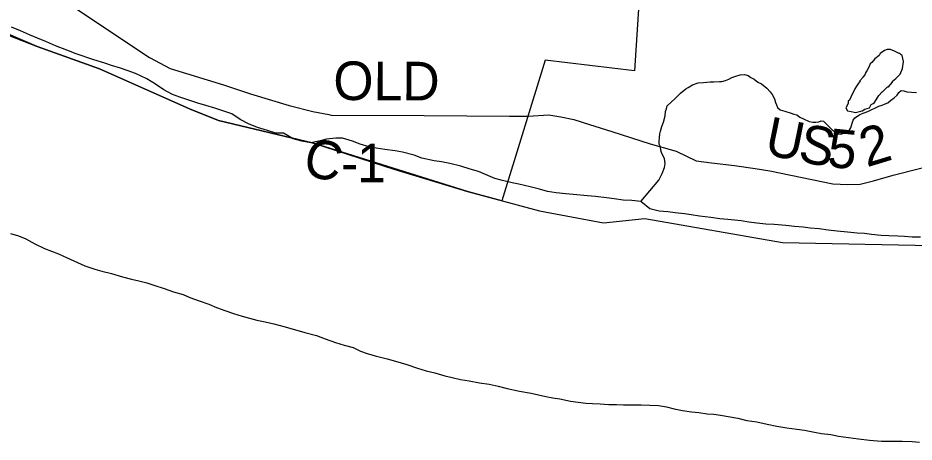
# Model space of a CAD drawing. Extents: x 1949938.81 to 1949945.61, y 152207.65 to 152214.09.
# Drawn here: x 1949941.387 to 1949942.704, y 152207.717 to 152208.341 of the extents above; entities that cross this region are included whole.
import ezdxf

# ---------------------------------------------------------------- set-up
doc = ezdxf.new("R2010")
doc.units = 0
for name, color, linetype in [('GM_X_City_Street', 7, 'Continuous'), ('GM_X_Corporation', 7, 'Continuous'), ('GM_X_County', 7, 'Continuous'), ('GM_X_County_Road', 7, 'Continuous'), ('GM_X_County_Road_Text', 7, 'Continuous'), ('GM_X_Major_River', 7, 'Continuous'), ('GM_X_Minor_Lake', 7, 'Continuous'), ('GM_X_Minor_River', 7, 'Continuous'), ('GM_X_Township', 7, 'Continuous')]:
    doc.layers.add(name, color=color, linetype=linetype)

msp = doc.modelspace()

# ---------------------------------------------------------------- linework, layer by layer
at = {"layer": 'GM_X_City_Street'}
msp.add_lwpolyline([(1949941.4607, 152208.3637), (1949941.4704, 152208.3561), (1949941.5442, 152208.3067), (1949941.5804, 152208.2827), (1949941.6108, 152208.2664), (1949941.689, 152208.2426), (1949941.7287, 152208.2292), (1949941.7858, 152208.2124), (1949941.8203, 152208.2034), (1949941.8437, 152208.1989)], dxfattribs=at)
at = {"layer": 'GM_X_Corporation'}
msp.add_lwpolyline([(1949942.1062, 152209.4059), (1949942.0896, 152209.1325), (1949942.3484, 152209.1187), (1949942.2928, 152208.2633), (1949942.1618, 152208.279), (1949942.0982, 152208.0722), (1949942.0477, 152208.0858), (1949941.8214, 152208.1567), (1949941.682, 152208.19), (1949941.6393, 152208.2075), (1949941.5072, 152208.2663), (1949941.4156, 152208.2992), (1949941.1468, 152208.4145), (1949940.9962, 152208.5094), (1949940.8932, 152208.5894), (1949940.8285, 152208.6338), (1949940.6601, 152208.7875), (1949940.5757, 152208.8589), (1949940.4882, 152208.9716), (1949940.3947, 152209.1158), (1949940.3383, 152209.2145)], dxfattribs=at)
at = {"layer": 'GM_X_County'}
msp.add_lwpolyline([(1949940.3383, 152209.2145), (1949940.3947, 152209.1158), (1949940.4882, 152208.9716), (1949940.5757, 152208.8589), (1949940.6601, 152208.7875), (1949940.8285, 152208.6338), (1949940.8932, 152208.5894), (1949940.9962, 152208.5094), (1949941.1468, 152208.4145), (1949941.2284, 152208.3724), (1949941.4156, 152208.2992), (1949941.5072, 152208.2663), (1949941.6393, 152208.2075), (1949941.682, 152208.19), (1949941.8214, 152208.1567), (1949941.9395, 152208.1188), (1949942.0477, 152208.0858), (1949942.1534, 152208.0573), (1949942.2476, 152208.0399), (1949942.3082, 152208.046), (1949942.5103, 152208.0107), (1949942.8268, 152208.0046)], dxfattribs=at)
at = {"layer": 'GM_X_County_Road'}
msp.add_lwpolyline([(1949941.8437, 152208.1989), (1949941.8476, 152208.1981), (1949941.9841, 152208.1975), (1949942.1095, 152208.1966), (1949942.1364, 152208.1966), (1949942.1671, 152208.1984), (1949942.1849, 152208.1956), (1949942.2041, 152208.1914), (1949942.227, 152208.1844), (1949942.2598, 152208.1741), (1949942.316, 152208.1558), (1949942.3541, 152208.145), (1949942.3838, 152208.131), (1949942.406, 152208.1277), (1949942.4398, 152208.124), (1949942.4703, 152208.1195), (1949942.4917, 152208.1162), (1949942.5844, 152208.0972), (1949942.6061, 152208.0962), (1949942.6245, 152208.0966), (1949942.6444, 152208.1013), (1949942.6732, 152208.1097), (1949942.7524, 152208.1298)], dxfattribs=at)
at = {"layer": 'GM_X_Major_River'}
for points in [[(1949942.0877, 152208.105), (1949942.0639, 152208.1152), (1949942.0518, 152208.1186), (1949942.0378, 152208.1232), (1949942.0215, 152208.127), (1949942.0094, 152208.1293), (1949941.9988, 152208.1308), (1949941.9807, 152208.135), (1949941.9693, 152208.1391), (1949941.9523, 152208.1437), (1949941.9413, 152208.1456), (1949941.9262, 152208.1475), (1949941.9134, 152208.1497), (1949941.9031, 152208.1516), (1949941.8899, 152208.1554), (1949941.8786, 152208.1596), (1949941.8642, 152208.1641), (1949941.8544, 152208.1641), (1949941.8407, 152208.1626), (1949941.829, 152208.1596), (1949941.8173, 152208.1573), (1949941.8044, 152208.16), (1949941.7916, 152208.1634), (1949941.7773, 152208.1716), (1949941.7659, 152208.1713), (1949941.7538, 152208.1755), (1949941.739, 152208.1797), (1949941.7258, 152208.1854), (1949941.7137, 152208.1918), (1949941.7012, 152208.1998), (1949941.688, 152208.2043), (1949941.6762, 152208.2085), (1949941.663, 152208.2123), (1949941.6517, 152208.2157), (1949941.6414, 152208.2191), (1949941.6248, 152208.2244), (1949941.6142, 152208.2282), (1949941.6017, 152208.2354), (1949941.5893, 152208.2434), (1949941.5764, 152208.2514), (1949941.5598, 152208.2593), (1949941.5477, 152208.2639), (1949941.5378, 152208.2669), (1949941.5246, 152208.2711), (1949941.5148, 152208.2745), (1949941.4989, 152208.2794), (1949941.4728, 152208.2881), (1949941.4592, 152208.2935), (1949941.4425, 152208.2999), (1949941.4293, 152208.3056), (1949941.4157, 152208.3113), (1949941.4043, 152208.3162), (1949941.3907, 152208.3219), (1949941.3779, 152208.3272)], [(1949942.7132, 152208.0188), (1949942.7011, 152208.0188), (1949942.6898, 152208.0196), (1949942.6799, 152208.02), (1949942.6667, 152208.0207), (1949942.6554, 152208.0211), (1949942.6414, 152208.0226), (1949942.6308, 152208.0238), (1949942.6202, 152208.0245), (1949942.6062, 152208.0261), (1949942.5907, 152208.0276), (1949942.5775, 152208.0291), (1949942.5646, 152208.031), (1949942.551, 152208.0321), (1949942.5408, 152208.0333), (1949942.5283, 152208.0344), (1949942.5154, 152208.0356), (1949942.498, 152208.0371), (1949942.4859, 152208.0378), (1949942.4727, 152208.0394), (1949942.461, 152208.0409), (1949942.4496, 152208.0424), (1949942.43, 152208.0447), (1949942.4186, 152208.0458), (1949942.4054, 152208.0477), (1949942.3884, 152208.0496), (1949942.3763, 152208.0515), (1949942.3664, 152208.053), (1949942.3528, 152208.0545), (1949942.3422, 152208.0557), (1949942.3294, 152208.0568), (1949942.3157, 152208.0602), (1949942.3025, 152208.0712), (1949942.2889, 152208.0727), (1949942.2764, 152208.0731), (1949942.2632, 152208.075), (1949942.2518, 152208.0765), (1949942.2356, 152208.0784), (1949942.2242, 152208.0796), (1949942.203, 152208.0815), (1949942.1921, 152208.0822), (1949942.1781, 152208.0837), (1949942.1652, 152208.086), (1949942.1535, 152208.0891), (1949942.1395, 152208.0925), (1949942.1232, 152208.0966), (1949942.1134, 152208.0985), (1949942.099, 152208.102), (1949942.0877, 152208.105)], [(1949941.3763, 152208.0238), (1949941.388, 152208.0207), (1949941.3986, 152208.0162), (1949941.4118, 152208.009), (1949941.4262, 152208.0021), (1949941.4364, 152207.998), (1949941.4466, 152207.9942), (1949941.4595, 152207.9881), (1949941.4693, 152207.9839), (1949941.4856, 152207.9767)], [(1949941.4856, 152207.9767), (1949941.4999, 152207.9714), (1949941.5105, 152207.9684), (1949941.5245, 152207.965), (1949941.5408, 152207.9604), (1949941.554, 152207.957), (1949941.565, 152207.9544), (1949941.5767, 152207.9517), (1949941.5869, 152207.9479), (1949941.602, 152207.943), (1949941.6156, 152207.9384), (1949941.63, 152207.9343), (1949941.6398, 152207.9297), (1949941.6535, 152207.9252), (1949941.6675, 152207.9199), (1949941.6788, 152207.9153), (1949941.6913, 152207.9108), (1949941.7041, 152207.9062), (1949941.7166, 152207.9024), (1949941.7276, 152207.8994), (1949941.7382, 152207.8967), (1949941.7506, 152207.8941), (1949941.7631, 152207.891), (1949941.7779, 152207.8873), (1949941.7934, 152207.8827), (1949941.8085, 152207.8785), (1949941.8259, 152207.874), (1949941.8384, 152207.8691), (1949941.8535, 152207.8637), (1949941.8664, 152207.86), (1949941.8796, 152207.8562), (1949941.8906, 152207.8512), (1949941.9004, 152207.8474), (1949941.9121, 152207.844), (1949941.9295, 152207.8395), (1949941.942, 152207.8361), (1949941.9583, 152207.8315), (1949941.9742, 152207.8262), (1949941.987, 152207.822), (1949941.9995, 152207.8194), (1949942.0146, 152207.8148), (1949942.0252, 152207.8122), (1949942.0373, 152207.8095), (1949942.0502, 152207.8076), (1949942.0653, 152207.8046), (1949942.0797, 152207.8023), (1949942.0925, 152207.7997), (1949942.1061, 152207.7959), (1949942.1243, 152207.7921), (1949942.1413, 152207.7891), (1949942.1519, 152207.7868), (1949942.1629, 152207.7845), (1949942.1731, 152207.7822), (1949942.1833, 152207.7807), (1949942.1992, 152207.7777), (1949942.2105, 152207.7758), (1949942.2215, 152207.7746), (1949942.2313, 152207.7739), (1949942.2427, 152207.7735), (1949942.2552, 152207.7727), (1949942.2665, 152207.7727), (1949942.2767, 152207.772), (1949942.3028, 152207.772), (1949942.3157, 152207.7716), (1949942.3282, 152207.7709), (1949942.3399, 152207.769), (1949942.3512, 152207.7663), (1949942.3637, 152207.764), (1949942.3769, 152207.7617), (1949942.3875, 152207.7606), (1949942.3996, 152207.7591), (1949942.4095, 152207.7583), (1949942.4193, 152207.7568), (1949942.445, 152207.7523), (1949942.4582, 152207.7492), (1949942.4726, 152207.7469), (1949942.4881, 152207.7435), (1949942.5021, 152207.7405), (1949942.5169, 152207.7382), (1949942.5316, 152207.7363), (1949942.543, 152207.7348), (1949942.5573, 152207.7318), (1949942.5679, 152207.7299), (1949942.5815, 152207.7283), (1949942.5929, 152207.7261), (1949942.622, 152207.7219), (1949942.6383, 152207.7204), (1949942.656, 152207.7189), (1949942.6715, 152207.7185), (1949942.6863, 152207.7185), (1949942.701, 152207.7181), (1949942.712, 152207.7173)]]:
    msp.add_lwpolyline(points, dxfattribs=at)
at = {"layer": 'GM_X_Minor_Lake'}
for points in [[(1949942.675, 152208.2919), (1949942.6694, 152208.2946), (1949942.6641, 152208.2946), (1949942.6603, 152208.293), (1949942.6538, 152208.2885), (1949942.6523, 152208.2859), (1949942.6463, 152208.2806), (1949942.6417, 152208.2756), (1949942.6395, 152208.2734), (1949942.6376, 152208.2696), (1949942.6345, 152208.2631), (1949942.6326, 152208.2601), (1949942.6326, 152208.2597), (1949942.6315, 152208.2574), (1949942.6285, 152208.2537), (1949942.6285, 152208.2533), (1949942.6243, 152208.2483), (1949942.6247, 152208.2487), (1949942.6213, 152208.2434), (1949942.6194, 152208.2408), (1949942.6167, 152208.2366), (1949942.6111, 152208.2245), (1949942.6088, 152208.2199), (1949942.6069, 152208.2188), (1949942.6069, 152208.215), (1949942.6035, 152208.2086)], [(1949942.6035, 152208.2086), (1949942.6058, 152208.2044), (1949942.6114, 152208.2036), (1949942.6156, 152208.2025), (1949942.6175, 152208.2017), (1949942.6277, 152208.2044), (1949942.6315, 152208.2066), (1949942.6383, 152208.2089), (1949942.6409, 152208.2138), (1949942.6436, 152208.2153), (1949942.6455, 152208.2165), (1949942.6519, 152208.2267), (1949942.6568, 152208.2324), (1949942.6568, 152208.2316), (1949942.6648, 152208.2399), (1949942.6663, 152208.2396), (1949942.672, 152208.2464), (1949942.6723, 152208.2479), (1949942.6769, 152208.2517), (1949942.6799, 152208.2547), (1949942.6833, 152208.2581), (1949942.6867, 152208.2665), (1949942.6882, 152208.2763), (1949942.6882, 152208.2771), (1949942.6864, 152208.2858), (1949942.6849, 152208.2866), (1949942.683, 152208.2885), (1949942.6818, 152208.2885), (1949942.675, 152208.2919)]]:
    msp.add_lwpolyline(points, dxfattribs=at)
at = {"layer": 'GM_X_Minor_River'}
msp.add_lwpolyline([(1949942.3025, 152208.0712), (1949942.3286, 152208.1023), (1949942.3337, 152208.1121), (1949942.3369, 152208.1212), (1949942.3381, 152208.1268), (1949942.3371, 152208.1341), (1949942.3346, 152208.1387), (1949942.3327, 152208.1433), (1949942.3317, 152208.1467), (1949942.331, 152208.1516), (1949942.3295, 152208.1555), (1949942.3292, 152208.1593), (1949942.3297, 152208.1653), (1949942.3302, 152208.1706), (1949942.3314, 152208.1744), (1949942.333, 152208.1812), (1949942.3354, 152208.1876), (1949942.3379, 152208.1971), (1949942.3387, 152208.2035), (1949942.3399, 152208.2073), (1949942.3411, 152208.2115), (1949942.3527, 152208.2227), (1949942.3604, 152208.2305), (1949942.3685, 152208.2368), (1949942.3719, 152208.2387), (1949942.3784, 152208.2427), (1949942.3864, 152208.2453), (1949942.3944, 152208.2459), (1949942.4043, 152208.2468), (1949942.4096, 152208.2471), (1949942.4179, 152208.2474), (1949942.4213, 152208.2477), (1949942.4267, 152208.2491), (1949942.4316, 152208.2509), (1949942.4358, 152208.2532), (1949942.4419, 152208.2553), (1949942.4484, 152208.2575), (1949942.4548, 152208.2578), (1949942.4601, 152208.2562), (1949942.4639, 152208.2534), (1949942.4691, 152208.2511), (1949942.474, 152208.2464), (1949942.4796, 152208.2441), (1949942.4874, 152208.2375), (1949942.4923, 152208.2321), (1949942.4952, 152208.2286), (1949942.4985, 152208.2221), (1949942.5, 152208.2168), (1949942.5018, 152208.2133), (1949942.5029, 152208.2095), (1949942.507, 152208.206), (1949942.5104, 152208.2048), (1949942.5137, 152208.204), (1949942.5232, 152208.2008), (1949942.5269, 152208.1996), (1949942.5315, 152208.1984), (1949942.5359, 152208.1949), (1949942.5412, 152208.1925), (1949942.5495, 152208.1886), (1949942.5551, 152208.1877), (1949942.5597, 152208.1876), (1949942.5639, 152208.1883), (1949942.5673, 152208.1898), (1949942.5707, 152208.1894), (1949942.5744, 152208.1855), (1949942.5781, 152208.182), (1949942.5837, 152208.1762), (1949942.5878, 152208.1735), (1949942.5927, 152208.1708), (1949942.5961, 152208.1703), (1949942.6026, 152208.1721), (1949942.6064, 152208.1724), (1949942.6107, 152208.1792), (1949942.6127, 152208.186), (1949942.6143, 152208.1905), (1949942.6166, 152208.1939), (1949942.6208, 152208.1965), (1949942.6243, 152208.1991), (1949942.6289, 152208.2009), (1949942.6357, 152208.2034), (1949942.6399, 152208.2053), (1949942.6483, 152208.2093), (1949942.6518, 152208.2111), (1949942.6567, 152208.2126), (1949942.6613, 152208.2148), (1949942.6651, 152208.2162), (1949942.6693, 152208.2196), (1949942.6747, 152208.2237), (1949942.6789, 152208.2274), (1949942.6813, 152208.2311), (1949942.6847, 152208.2345), (1949942.6889, 152208.2337), (1949942.6934, 152208.2321), (1949942.6999, 152208.2316), (1949942.7074, 152208.2311)], dxfattribs=at)
at = {"layer": 'GM_X_Township'}
msp.add_lwpolyline([(1949941.2812, 152209.1802), (1949941.2628, 152209.0777), (1949941.2592, 152209.0126), (1949941.251, 152208.8752), (1949941.2495, 152208.8499), (1949941.2462, 152208.7948), (1949941.2377, 152208.5233), (1949941.2284, 152208.3724), (1949941.4156, 152208.2992), (1949941.5072, 152208.2663), (1949941.6393, 152208.2075), (1949941.682, 152208.19), (1949941.8214, 152208.1567), (1949941.9395, 152208.1188), (1949942.0477, 152208.0858), (1949942.1534, 152208.0573), (1949942.2476, 152208.0399), (1949942.3082, 152208.046), (1949942.5103, 152208.0107), (1949942.8268, 152208.0046)], dxfattribs=at)

# ---------------------------------------------------------------- texts
at = {"layer": 'GM_X_County_Road_Text'}
for s, height, rotation, p in [('OLD', 0.05682, 359.6649, (1949941.8504, 152208.2204)), ('U', 0.0568, 348.5197, (1949942.4822, 152208.1407)), ('S', 0.0568, 348.721, (1949942.5315, 152208.1307)), ('5', 0.0568, 354.1077, (1949942.5748, 152208.1224)), ('2', 0.0568, 16.9199, (1949942.6341, 152208.1211)), ('C', 0.0568, 348.4496, (1949941.804, 152208.1101)), ('1', 0.0568, 359.7307, (1949941.8853, 152208.0994)), ('-', 0.0568, 359.8911, (1949941.862, 152208.0995))]:
    msp.add_text(s, height=height, rotation=rotation, dxfattribs=at).set_placement(p)

doc.saveas('drawing.dxf')
